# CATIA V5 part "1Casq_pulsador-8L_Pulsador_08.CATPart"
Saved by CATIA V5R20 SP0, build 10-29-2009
Part number: 1Casq_pulsador-8L_Pulsador_08
Revision: ANY
Definition: UNKNOWN
Nomenclature: 1Casq_pulsador-8L_Pulsador_08
Source: Unknown
Bounding box of the stored display mesh (mm): x -7.604 to 7.604, y 0 to 15.3, z -7.8 to 7.8
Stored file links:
  C:\Users\Utente\Desktop\IO LAVORO\3D X SITO CF\CUMSA\3D files BA\BA 081620\1Casq_pulsador-8L_Pulsador_08.CATPart
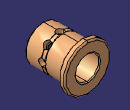
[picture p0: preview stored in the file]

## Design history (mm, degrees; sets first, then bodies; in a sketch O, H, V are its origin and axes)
Body1 "MatrizC1" (main body)
  Solid1: solid without history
